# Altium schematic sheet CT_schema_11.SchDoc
size 391 x 238 mm
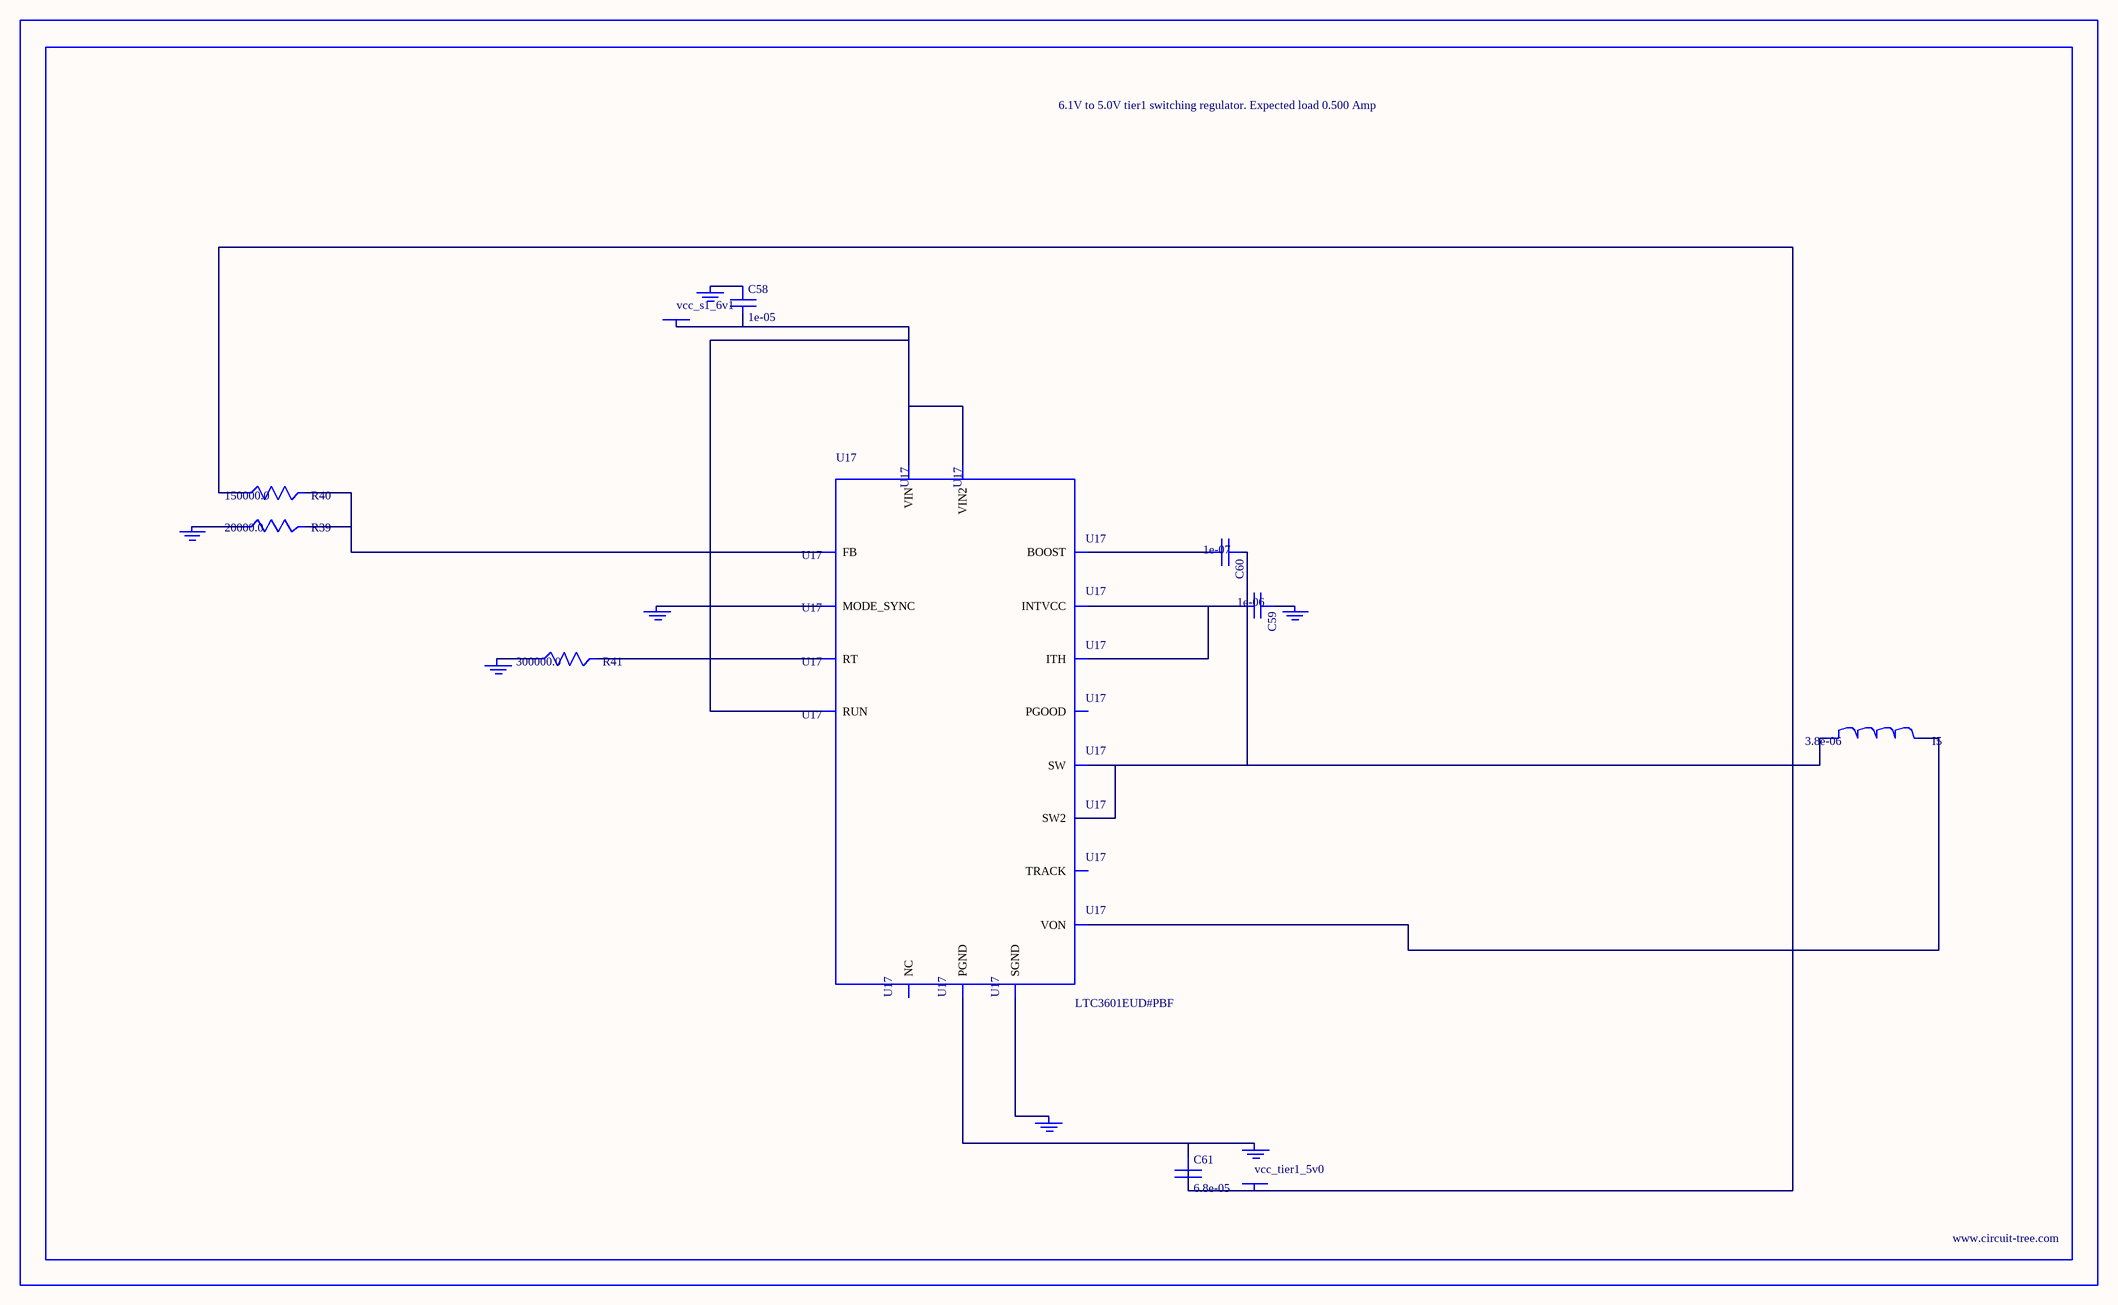
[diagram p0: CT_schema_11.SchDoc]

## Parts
BORDER10  (no value)
C58  1e-05  [C0805]
C59  1e-06  [C0603]
C60  1e-07  [C0402]
C61  6.8e-05  [2220]
GND_INSTANCE_10_0  (no value)
GND_INSTANCE_10_1  (no value)
GND_INSTANCE_10_2  (no value)
GND_INSTANCE_10_3  (no value)
GND_INSTANCE_10_4  (no value)
GND_INSTANCE_10_5  (no value)
GND_INSTANCE_10_6  (no value)
I5  3.8e-06  [DR1040]
POWER_INSTANCE_10_0  vcc_s1_6v1
POWER_INSTANCE_10_1  vcc_tier1_5v0
R39  20000.0  [R0603]
R40  150000.0  [R0603]
R41  300000.0  [R0603]
U17  LTC3601EUD#PBF  [QFN-16_EP]

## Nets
NetC58_1: C58.1 GND_INSTANCE_10_5.0(GND)
NetC58_2: C58.2 POWER_INSTANCE_10_0.0(PWR) U17.14(RUN) U17.15(VIN) U17.16(VIN2)
NetC59_1: C59.1 GND_INSTANCE_10_1.0(GND)
NetC59_2: C59.2 U17.7(INTVCC) U17.12(ITH)
NetC60_1: C60.1 I5.1 U17.3(SW) U17.4(SW2)
NetC60_2: C60.2 U17.6(BOOST)
NetC61_1: C61.1 GND_INSTANCE_10_6.0(GND) U17.17(PGND)
NetC61_2: C61.2 I5.2 POWER_INSTANCE_10_1.0(PWR) R40.1 U17.8(VON)
NetGND_INSTANCE_10_0_0: GND_INSTANCE_10_0.0(GND) U17.1(MODE_SYNC)
NetGND_INSTANCE_10_2_0: GND_INSTANCE_10_2.0(GND) U17.9(SGND)
NetGND_INSTANCE_10_3_0: GND_INSTANCE_10_3.0(GND) R41.1
NetGND_INSTANCE_10_4_0: GND_INSTANCE_10_4.0(GND) R39.1
NetR39_2: R39.2 R40.2 U17.11(FB)
NetR41_2: R41.2 U17.10(RT)

Not connected (* = marked no-connect by the designer): U17 2(PGOOD) 5(NC) 13(TRACK)

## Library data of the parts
BORDER10 = BORDER_PAGE10
C58 = C0805C106K8RACTU
C59 = C0603C105K3RACTU
C60 = C0402C104K3RACTU
C61 = C5750X5R1A686M
GND_INSTANCE_10_0-GND_INSTANCE_10_6 = GND
I5 = DR1040-3R8-R
POWER_INSTANCE_10_0 POWER_INSTANCE_10_1 = PWR
R39 = RC0603JR-0720KL
R40 = RC0603JR-07150KL
R41 = RC0603JR-07300KL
